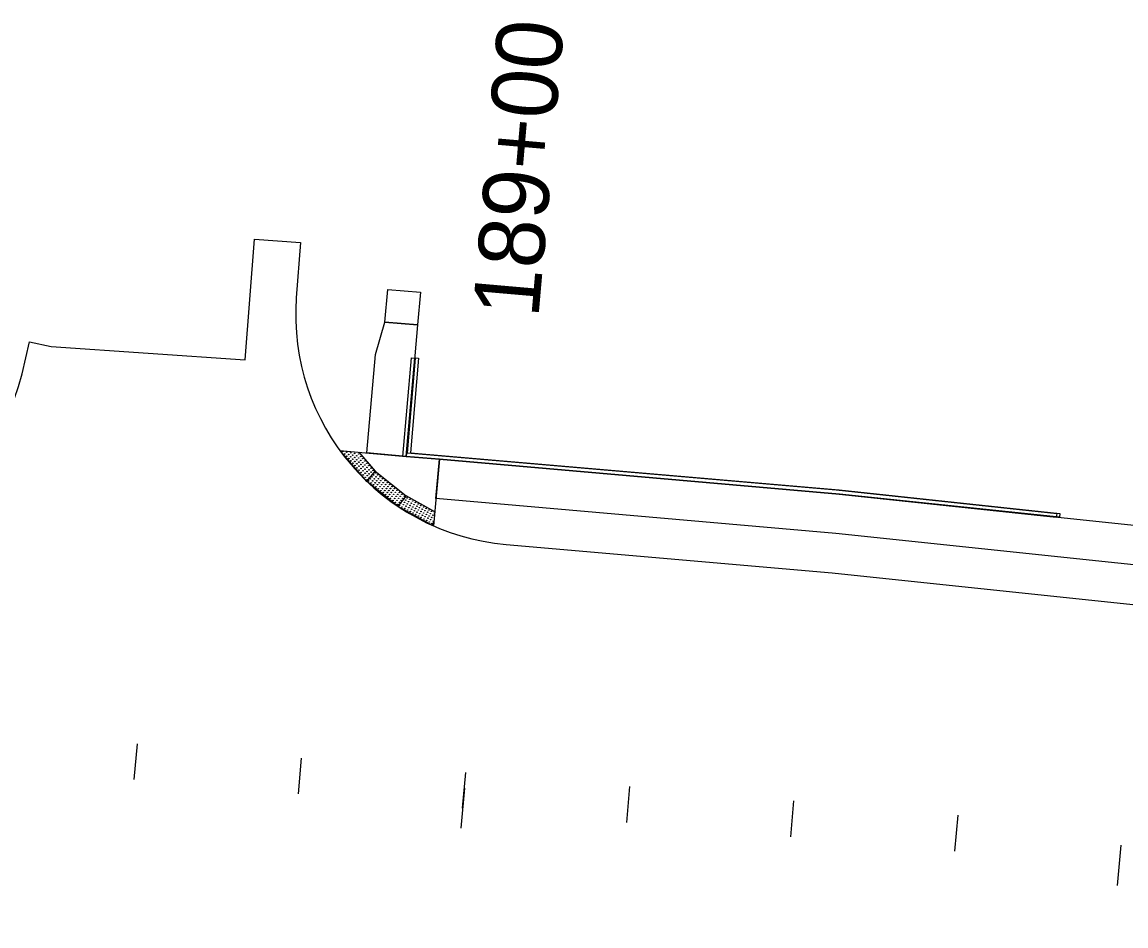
# Model space of a CAD drawing. Extents: x 20499216 to 20505321, y 7953487 to 7960535.
# Drawn here: x 20502538.4 to 20502705.9, y 7953802.5 to 7953939.7 of the extents above; entities that cross this region are included whole.
import ezdxf

# ---------------------------------------------------------------- set-up
doc = ezdxf.new("R2010")
doc.units = 0
for name, color, linetype in [('Drainage', 7, 'Continuous'), ('EXT_CU', 7, 'Continuous'), ('EXT_RR', 7, 'Continuous'), ('EXT_SNP', 7, 'Continuous'), ('NamedBoundary', 7, 'Continuous'), ('Roadways', 7, 'Continuous'), ('Safety', 7, 'Continuous')]:
    doc.layers.add(name, color=color, linetype=linetype)

msp = doc.modelspace()

# ---------------------------------------------------------------- linework, layer by layer
at = {"layer": 'Drainage'}
msp.add_lwpolyline([(20502593.51, 7953894.14), (20502598.46, 7953893.73), (20502596.74, 7953873.78), (20502590.76, 7953874.3), (20502592.07, 7953889.26)], close=True, dxfattribs=at)
at = {"layer": 'EXT_CU'}
for p, q in [((20502586.81, 7953874.5), (20502586.96, 7953874.63)), ((20502590.77, 7953869.99), (20502586.81, 7953874.5)), ((20502589.55, 7953874.41), (20502592.02, 7953871.55)), ((20502590.77, 7953869.99), (20502592.02, 7953871.55)), ((20502592.02, 7953871.55), (20502596.7, 7953867.79)), ((20502595.44, 7953866.23), (20502590.77, 7953869.99)), ((20502596.7, 7953867.79), (20502595.44, 7953866.23)), ((20502601.06, 7953865.39), (20502596.7, 7953867.79)), ((20502595.44, 7953866.23), (20502600.69, 7953863.32)), ((20502600.69, 7953863.32), (20502600.92, 7953863.74))]:
    msp.add_line(p, q, dxfattribs=at)
for points in [[(20502598.61, 7953888.68), (20502597.37, 7953874.31), (20502662.45, 7953868.69), (20502695.94, 7953865.1), (20502695.88, 7953864.54), (20502662.5, 7953868.05), (20502596.74, 7953873.78), (20502598.03, 7953888.73)], [(20502662.5, 7953868.05), (20502961.27, 7953836.6), (20503020.68, 7953827.63), (20503141.39, 7953813.56), (20503176.54, 7953810.63), (20503176.04, 7953804.65), (20503140.79, 7953807.58), (20503019.89, 7953821.68), (20502960.51, 7953830.65), (20502661.92, 7953862.08), (20502601.24, 7953867.37), (20502601.76, 7953873.35)]]:
    msp.add_lwpolyline(points, close=True, dxfattribs=at)
for centre, major_axis in [((20502587.09, 7953874.52), (0.0298, -0.0337)), ((20502587.09, 7953874.52), (0.0149, -0.0169)), ((20502587.4, 7953874.16), (0.0298, -0.0337)), ((20502587.4, 7953874.16), (0.0149, -0.0169)), ((20502587.69, 7953874.42), (0.0298, -0.0337)), ((20502587.71, 7953873.81), (0.0298, -0.0337)), ((20502587.69, 7953874.42), (0.0149, -0.0169)), ((20502587.71, 7953873.81), (0.0149, -0.0169)), ((20502588, 7953874.07), (0.0298, -0.0337)), ((20502588, 7953874.07), (0.0149, -0.0169)), ((20502588.3, 7953874.33), (0.0298, -0.0337)), ((20502588.3, 7953874.33), (0.0149, -0.0169)), ((20502588.31, 7953873.72), (0.0298, -0.0337)), ((20502588.31, 7953873.72), (0.0149, -0.0169)), ((20502588.61, 7953873.97), (0.0298, -0.0337)), ((20502588.61, 7953873.97), (0.0149, -0.0169)), ((20502588.9, 7953874.23), (0.0298, -0.0337)), ((20502588.92, 7953873.62), (0.0298, -0.0337)), ((20502588.9, 7953874.23), (0.0149, -0.0169)), ((20502588.92, 7953873.62), (0.0149, -0.0169)), ((20502589.21, 7953873.88), (0.0298, -0.0337)), ((20502589.21, 7953873.88), (0.0149, -0.0169)), ((20502589.51, 7953874.14), (0.0298, -0.0337)), ((20502589.51, 7953874.14), (0.0149, -0.0169)), ((20502589.82, 7953873.78), (0.0298, -0.0337)), ((20502589.82, 7953873.78), (0.0149, -0.0169)), ((20502588.02, 7953873.46), (0.0298, -0.0337)), ((20502588.02, 7953873.46), (0.0149, -0.0169)), ((20502588.33, 7953873.1), (0.0298, -0.0337)), ((20502588.33, 7953873.1), (0.0149, -0.0169)), ((20502588.62, 7953873.36), (0.0298, -0.0337)), ((20502588.64, 7953872.75), (0.0298, -0.0337)), ((20502588.62, 7953873.36), (0.0149, -0.0169)), ((20502588.64, 7953872.75), (0.0149, -0.0169)), ((20502588.93, 7953873.01), (0.0298, -0.0337)), ((20502588.95, 7953872.4), (0.0298, -0.0337)), ((20502588.93, 7953873.01), (0.0149, -0.0169)), ((20502588.95, 7953872.4), (0.0149, -0.0169)), ((20502589.23, 7953873.27), (0.0298, -0.0337)), ((20502589.23, 7953873.27), (0.0149, -0.0169)), ((20502589.24, 7953872.66), (0.0298, -0.0337)), ((20502589.26, 7953872.04), (0.0298, -0.0337)), ((20502589.24, 7953872.66), (0.0149, -0.0169)), ((20502589.26, 7953872.04), (0.0149, -0.0169)), ((20502589.52, 7953873.53), (0.0298, -0.0337)), ((20502589.54, 7953872.91), (0.0298, -0.0337)), ((20502589.52, 7953873.53), (0.0149, -0.0169)), ((20502589.54, 7953872.91), (0.0149, -0.0169)), ((20502589.55, 7953872.3), (0.0298, -0.0337)), ((20502589.55, 7953872.3), (0.0149, -0.0169)), ((20502589.83, 7953873.17), (0.0298, -0.0337)), ((20502589.85, 7953872.56), (0.0298, -0.0337)), ((20502589.83, 7953873.17), (0.0149, -0.0169)), ((20502589.85, 7953872.56), (0.0149, -0.0169)), ((20502589.86, 7953871.95), (0.0298, -0.0337)), ((20502589.86, 7953871.95), (0.0149, -0.0169)), ((20502590.13, 7953873.43), (0.0298, -0.0337)), ((20502590.13, 7953873.43), (0.0149, -0.0169)), ((20502590.14, 7953872.82), (0.0298, -0.0337)), ((20502590.16, 7953872.21), (0.0298, -0.0337)), ((20502590.14, 7953872.82), (0.0149, -0.0169)), ((20502590.16, 7953872.21), (0.0149, -0.0169)), ((20502590.44, 7953873.08), (0.0298, -0.0337)), ((20502590.44, 7953873.08), (0.0149, -0.0169)), ((20502590.45, 7953872.47), (0.0298, -0.0337)), ((20502590.47, 7953871.85), (0.0298, -0.0337)), ((20502590.45, 7953872.47), (0.0149, -0.0169)), ((20502590.75, 7953872.72), (0.0298, -0.0337)), ((20502590.75, 7953872.72), (0.0149, -0.0169)), ((20502590.76, 7953872.11), (0.0298, -0.0337)), ((20502590.76, 7953872.11), (0.0149, -0.0169)), ((20502591.06, 7953872.37), (0.0298, -0.0337)), ((20502591.06, 7953872.37), (0.0149, -0.0169)), ((20502591.38, 7953872), (0.0298, -0.0337)), ((20502591.38, 7953872), (0.0149, -0.0169)), ((20502589.57, 7953871.69), (0.0298, -0.0337)), ((20502589.57, 7953871.69), (0.0149, -0.0169)), ((20502589.88, 7953871.34), (0.0298, -0.0337)), ((20502589.88, 7953871.34), (0.0149, -0.0169)), ((20502590.17, 7953871.6), (0.0298, -0.0337)), ((20502590.17, 7953871.6), (0.0149, -0.0169)), ((20502590.2, 7953870.97), (0.0298, -0.0337)), ((20502590.2, 7953870.97), (0.0149, -0.0169)), ((20502590.47, 7953871.85), (0.0149, -0.0169)), ((20502590.5, 7953871.22), (0.0298, -0.0337)), ((20502590.51, 7953870.61), (0.0298, -0.0337)), ((20502590.5, 7953871.22), (0.0149, -0.0169)), ((20502590.51, 7953870.61), (0.0149, -0.0169)), ((20502590.79, 7953871.48), (0.0298, -0.0337)), ((20502590.81, 7953870.87), (0.0298, -0.0337)), ((20502590.79, 7953871.48), (0.0149, -0.0169)), ((20502590.82, 7953870.26), (0.0298, -0.0337)), ((20502590.81, 7953870.87), (0.0149, -0.0169)), ((20502590.82, 7953870.26), (0.0149, -0.0169)), ((20502591.09, 7953871.74), (0.0298, -0.0337)), ((20502591.1, 7953871.13), (0.0298, -0.0337)), ((20502591.09, 7953871.74), (0.0149, -0.0169)), ((20502591.12, 7953870.52), (0.0298, -0.0337)), ((20502591.1, 7953871.13), (0.0149, -0.0169)), ((20502591.12, 7953870.52), (0.0149, -0.0169)), ((20502591.28, 7953870.36), (0.0352, -0.0281)), ((20502591.28, 7953870.36), (0.0176, -0.014)), ((20502591.4, 7953871.39), (0.0298, -0.0337)), ((20502591.4, 7953871.39), (0.0149, -0.0169)), ((20502591.53, 7953870.67), (0.0352, -0.0281)), ((20502591.53, 7953870.67), (0.0176, -0.014)), ((20502591.69, 7953871.65), (0.0298, -0.0337)), ((20502591.69, 7953871.65), (0.0149, -0.0169)), ((20502591.78, 7953870.97), (0.0352, -0.0281)), ((20502591.78, 7953870.97), (0.0176, -0.014)), ((20502591.9, 7953870.37), (0.0352, -0.0281)), ((20502591.9, 7953870.37), (0.0176, -0.014)), ((20502592.02, 7953871.28), (0.0352, -0.0281)), ((20502592.02, 7953871.28), (0.0176, -0.014)), ((20502592.14, 7953870.68), (0.0352, -0.0281)), ((20502592.14, 7953870.68), (0.0176, -0.014)), ((20502592.39, 7953870.98), (0.0352, -0.0281)), ((20502592.39, 7953870.98), (0.0176, -0.014)), ((20502592.51, 7953870.38), (0.0352, -0.0281)), ((20502592.51, 7953870.38), (0.0176, -0.014)), ((20502592.75, 7953870.69), (0.0352, -0.0281)), ((20502592.75, 7953870.69), (0.0176, -0.014)), ((20502593.12, 7953870.39), (0.0352, -0.0281)), ((20502593.12, 7953870.39), (0.0176, -0.014)), ((20502591.04, 7953870.06), (0.0352, -0.0281)), ((20502591.04, 7953870.06), (0.0176, -0.014)), ((20502591.41, 7953869.76), (0.0352, -0.0281)), ((20502591.41, 7953869.76), (0.0176, -0.014)), ((20502591.65, 7953870.07), (0.0352, -0.0281)), ((20502591.65, 7953870.07), (0.0176, -0.014)), ((20502591.77, 7953869.47), (0.0352, -0.0281)), ((20502591.77, 7953869.47), (0.0176, -0.014)), ((20502592.02, 7953869.77), (0.0352, -0.0281)), ((20502592.02, 7953869.77), (0.0176, -0.014)), ((20502592.14, 7953869.17), (0.0352, -0.0281)), ((20502592.14, 7953869.17), (0.0176, -0.014)), ((20502592.26, 7953870.08), (0.0352, -0.0281)), ((20502592.26, 7953870.08), (0.0176, -0.014)), ((20502592.38, 7953869.48), (0.0352, -0.0281)), ((20502592.38, 7953869.48), (0.0176, -0.014)), ((20502592.5, 7953868.88), (0.0352, -0.0281)), ((20502592.5, 7953868.88), (0.0176, -0.014)), ((20502592.63, 7953869.78), (0.0352, -0.0281)), ((20502592.63, 7953869.78), (0.0176, -0.014)), ((20502592.75, 7953869.18), (0.0352, -0.0281)), ((20502592.75, 7953869.18), (0.0176, -0.014)), ((20502592.87, 7953868.58), (0.0352, -0.0281)), ((20502592.88, 7953870.09), (0.0352, -0.0281)), ((20502592.88, 7953870.09), (0.0176, -0.014)), ((20502592.87, 7953868.58), (0.0176, -0.014)), ((20502593, 7953869.49), (0.0352, -0.0281)), ((20502593, 7953869.49), (0.0176, -0.014)), ((20502593.12, 7953868.89), (0.0352, -0.0281)), ((20502593.12, 7953868.89), (0.0176, -0.014)), ((20502593.24, 7953869.79), (0.0352, -0.0281)), ((20502593.24, 7953869.79), (0.0176, -0.014)), ((20502593.36, 7953869.19), (0.0352, -0.0281)), ((20502593.36, 7953869.19), (0.0176, -0.014)), ((20502593.48, 7953868.59), (0.0352, -0.0281)), ((20502593.49, 7953870.1), (0.0352, -0.0281)), ((20502593.49, 7953870.1), (0.0176, -0.014)), ((20502593.48, 7953868.59), (0.0176, -0.014)), ((20502593.61, 7953869.5), (0.0352, -0.0281)), ((20502593.61, 7953869.5), (0.0176, -0.014)), ((20502593.73, 7953868.9), (0.0352, -0.0281)), ((20502593.73, 7953868.9), (0.0176, -0.014)), ((20502593.85, 7953869.8), (0.0352, -0.0281)), ((20502593.85, 7953869.8), (0.0176, -0.014)), ((20502593.97, 7953869.2), (0.0352, -0.0281)), ((20502593.97, 7953869.2), (0.0176, -0.014)), ((20502594.09, 7953868.6), (0.0352, -0.0281)), ((20502594.09, 7953868.6), (0.0176, -0.014)), ((20502594.22, 7953869.51), (0.0352, -0.0281)), ((20502594.22, 7953869.51), (0.0176, -0.014)), ((20502594.34, 7953868.91), (0.0352, -0.0281)), ((20502594.34, 7953868.91), (0.0176, -0.014)), ((20502594.59, 7953869.21), (0.0352, -0.0281)), ((20502594.59, 7953869.21), (0.0176, -0.014)), ((20502594.71, 7953868.61), (0.0352, -0.0281)), ((20502594.71, 7953868.61), (0.0176, -0.014)), ((20502594.95, 7953868.92), (0.0352, -0.0281)), ((20502594.95, 7953868.92), (0.0176, -0.014)), ((20502595.32, 7953868.63), (0.0352, -0.0281)), ((20502595.32, 7953868.63), (0.0176, -0.014)), ((20502593.24, 7953868.29), (0.0352, -0.0281)), ((20502593.24, 7953868.29), (0.0176, -0.014)), ((20502593.6, 7953867.99), (0.0352, -0.0281)), ((20502593.6, 7953867.99), (0.0176, -0.014)), ((20502593.85, 7953868.3), (0.0352, -0.0281)), ((20502593.85, 7953868.3), (0.0176, -0.014)), ((20502593.97, 7953867.7), (0.0352, -0.0281)), ((20502593.97, 7953867.7), (0.0176, -0.014)), ((20502594.21, 7953868), (0.0352, -0.0281)), ((20502594.21, 7953868), (0.0176, -0.014)), ((20502594.33, 7953867.41), (0.0352, -0.0281)), ((20502594.33, 7953867.41), (0.0176, -0.014)), ((20502594.46, 7953868.31), (0.0352, -0.0281)), ((20502594.46, 7953868.31), (0.0176, -0.014)), ((20502594.58, 7953867.71), (0.0352, -0.0281)), ((20502594.58, 7953867.71), (0.0176, -0.014)), ((20502594.72, 7953867.1), (0.0352, -0.0281)), ((20502594.72, 7953867.1), (0.0176, -0.014)), ((20502594.83, 7953868.02), (0.0352, -0.0281)), ((20502594.83, 7953868.02), (0.0176, -0.014)), ((20502594.97, 7953867.4), (0.0352, -0.0281)), ((20502594.97, 7953867.4), (0.0176, -0.014)), ((20502595.07, 7953868.32), (0.0352, -0.0281)), ((20502595.07, 7953868.32), (0.0176, -0.014)), ((20502595.21, 7953867.71), (0.0352, -0.0281)), ((20502595.21, 7953867.71), (0.0176, -0.014)), ((20502595.33, 7953867.11), (0.0352, -0.0281)), ((20502595.33, 7953867.11), (0.0176, -0.014)), ((20502595.46, 7953868.01), (0.0352, -0.0281)), ((20502595.46, 7953868.01), (0.0176, -0.014)), ((20502595.58, 7953867.41), (0.0352, -0.0281)), ((20502595.58, 7953867.41), (0.0176, -0.014)), ((20502595.7, 7953868.31), (0.0352, -0.0281)), ((20502595.7, 7953868.31), (0.0176, -0.014)), ((20502595.82, 7953867.72), (0.0352, -0.0281)), ((20502595.82, 7953867.72), (0.0176, -0.014)), ((20502595.94, 7953867.12), (0.0352, -0.0281)), ((20502595.94, 7953867.12), (0.0176, -0.014)), ((20502596.07, 7953868.02), (0.0352, -0.0281)), ((20502596.07, 7953868.02), (0.0176, -0.014)), ((20502596.19, 7953867.42), (0.0352, -0.0281)), ((20502596.19, 7953867.42), (0.0176, -0.014)), ((20502596.44, 7953867.73), (0.0352, -0.0281)), ((20502596.44, 7953867.73), (0.0176, -0.014)), ((20502596.67, 7953867.14), (-0.0393, 0.0219)), ((20502596.67, 7953867.14), (-0.0197, 0.0109)), ((20502596.86, 7953867.48), (-0.0393, 0.0219)), ((20502596.86, 7953867.48), (-0.0197, 0.0109)), ((20502597.08, 7953866.91), (-0.0393, 0.0219)), ((20502597.08, 7953866.91), (-0.0197, 0.0109)), ((20502597.27, 7953867.26), (-0.0393, 0.0219)), ((20502597.27, 7953867.26), (-0.0197, 0.0109)), ((20502597.7, 7953867.02), (-0.0393, 0.0219)), ((20502597.7, 7953867.02), (-0.0197, 0.0109)), ((20502595.09, 7953866.8), (0.0352, -0.0281)), ((20502595.09, 7953866.8), (0.0176, -0.014)), ((20502595.45, 7953866.51), (0.0352, -0.0281)), ((20502595.45, 7953866.51), (0.0176, -0.014)), ((20502595.69, 7953866.34), (-0.0393, 0.0219)), ((20502595.7, 7953866.81), (0.0352, -0.0281)), ((20502595.7, 7953866.81), (0.0176, -0.014)), ((20502595.69, 7953866.34), (-0.0197, 0.0109)), ((20502595.88, 7953866.68), (-0.0393, 0.0219)), ((20502595.88, 7953866.68), (-0.0197, 0.0109)), ((20502596.1, 7953866.11), (-0.0393, 0.0219)), ((20502596.1, 7953866.11), (-0.0197, 0.0109)), ((20502596.29, 7953866.45), (-0.0393, 0.0219)), ((20502596.29, 7953866.45), (-0.0197, 0.0109)), ((20502596.48, 7953866.8), (-0.0393, 0.0219)), ((20502596.48, 7953866.8), (-0.0197, 0.0109)), ((20502596.51, 7953865.88), (-0.0393, 0.0219)), ((20502596.51, 7953865.88), (-0.0197, 0.0109)), ((20502596.7, 7953866.23), (-0.0393, 0.0219)), ((20502596.7, 7953866.23), (-0.0197, 0.0109)), ((20502596.89, 7953866.57), (-0.0393, 0.0219)), ((20502596.89, 7953866.57), (-0.0197, 0.0109)), ((20502596.95, 7953865.64), (-0.0393, 0.0219)), ((20502596.95, 7953865.64), (-0.0197, 0.0109)), ((20502597.14, 7953865.99), (-0.0393, 0.0219)), ((20502597.14, 7953865.99), (-0.0197, 0.0109)), ((20502597.32, 7953866.33), (-0.0393, 0.0219)), ((20502597.32, 7953866.33), (-0.0197, 0.0109)), ((20502597.36, 7953865.42), (-0.0393, 0.0219)), ((20502597.36, 7953865.42), (-0.0197, 0.0109)), ((20502597.51, 7953866.67), (-0.0393, 0.0219)), ((20502597.51, 7953866.67), (-0.0197, 0.0109)), ((20502597.55, 7953865.76), (-0.0393, 0.0219)), ((20502597.55, 7953865.76), (-0.0197, 0.0109)), ((20502597.74, 7953866.1), (-0.0393, 0.0219)), ((20502597.74, 7953866.1), (-0.0197, 0.0109)), ((20502597.77, 7953865.19), (-0.0393, 0.0219)), ((20502597.77, 7953865.19), (-0.0197, 0.0109)), ((20502597.92, 7953866.45), (-0.0393, 0.0219)), ((20502597.92, 7953866.45), (-0.0197, 0.0109)), ((20502597.96, 7953865.53), (-0.0393, 0.0219)), ((20502597.96, 7953865.53), (-0.0197, 0.0109)), ((20502598.11, 7953866.79), (-0.0393, 0.0219)), ((20502598.11, 7953866.79), (-0.0197, 0.0109)), ((20502598.15, 7953865.88), (-0.0393, 0.0219)), ((20502598.15, 7953865.88), (-0.0197, 0.0109)), ((20502598.34, 7953866.22), (-0.0393, 0.0219)), ((20502598.34, 7953866.22), (-0.0197, 0.0109)), ((20502598.37, 7953865.31), (-0.0393, 0.0219)), ((20502598.37, 7953865.31), (-0.0197, 0.0109)), ((20502598.53, 7953866.56), (-0.0393, 0.0219)), ((20502598.53, 7953866.56), (-0.0197, 0.0109)), ((20502598.56, 7953865.65), (-0.0393, 0.0219)), ((20502598.56, 7953865.65), (-0.0197, 0.0109)), ((20502598.75, 7953865.99), (-0.0393, 0.0219)), ((20502598.75, 7953865.99), (-0.0197, 0.0109)), ((20502598.94, 7953866.33), (-0.0393, 0.0219)), ((20502598.94, 7953866.33), (-0.0197, 0.0109)), ((20502598.97, 7953865.42), (-0.0393, 0.0219)), ((20502598.97, 7953865.42), (-0.0197, 0.0109)), ((20502599.16, 7953865.76), (-0.0393, 0.0219)), ((20502599.16, 7953865.76), (-0.0197, 0.0109)), ((20502599.35, 7953866.11), (-0.0393, 0.0219)), ((20502599.35, 7953866.11), (-0.0197, 0.0109)), ((20502599.38, 7953865.19), (-0.0393, 0.0219)), ((20502599.38, 7953865.19), (-0.0197, 0.0109)), ((20502599.57, 7953865.54), (-0.0393, 0.0219)), ((20502599.57, 7953865.54), (-0.0197, 0.0109)), ((20502599.76, 7953865.88), (-0.0393, 0.0219)), ((20502599.76, 7953865.88), (-0.0197, 0.0109)), ((20502599.98, 7953865.31), (-0.0393, 0.0219)), ((20502599.98, 7953865.31), (-0.0197, 0.0109)), ((20502600.17, 7953865.65), (-0.0393, 0.0219)), ((20502600.17, 7953865.65), (-0.0197, 0.0109)), ((20502600.58, 7953865.43), (-0.0393, 0.0219)), ((20502600.58, 7953865.43), (-0.0197, 0.0109)), ((20502600.99, 7953865.2), (-0.0393, 0.0219)), ((20502600.99, 7953865.2), (-0.0197, 0.0109)), ((20502598.18, 7953864.96), (-0.0393, 0.0219)), ((20502598.18, 7953864.96), (-0.0197, 0.0109)), ((20502598.59, 7953864.74), (-0.0393, 0.0219)), ((20502598.59, 7953864.74), (-0.0197, 0.0109)), ((20502598.78, 7953865.08), (-0.0393, 0.0219)), ((20502598.78, 7953865.08), (-0.0197, 0.0109)), ((20502599, 7953864.51), (-0.0393, 0.0219)), ((20502599, 7953864.51), (-0.0197, 0.0109)), ((20502599.19, 7953864.85), (-0.0393, 0.0219)), ((20502599.19, 7953864.85), (-0.0197, 0.0109)), ((20502599.42, 7953864.28), (-0.0393, 0.0219)), ((20502599.42, 7953864.28), (-0.0197, 0.0109)), ((20502599.6, 7953864.62), (-0.0393, 0.0219)), ((20502599.6, 7953864.62), (-0.0197, 0.0109)), ((20502599.79, 7953864.97), (-0.0393, 0.0219)), ((20502599.79, 7953864.97), (-0.0197, 0.0109)), ((20502599.83, 7953864.05), (-0.0393, 0.0219)), ((20502599.83, 7953864.05), (-0.0197, 0.0109)), ((20502600.02, 7953864.4), (-0.0393, 0.0219)), ((20502600.02, 7953864.4), (-0.0197, 0.0109)), ((20502600.2, 7953864.74), (-0.0393, 0.0219)), ((20502600.2, 7953864.74), (-0.0197, 0.0109)), ((20502600.24, 7953863.83), (-0.0393, 0.0219)), ((20502600.24, 7953863.83), (-0.0197, 0.0109)), ((20502600.39, 7953865.08), (-0.0393, 0.0219)), ((20502600.39, 7953865.08), (-0.0197, 0.0109)), ((20502600.43, 7953864.17), (-0.0393, 0.0219)), ((20502600.43, 7953864.17), (-0.0197, 0.0109)), ((20502600.62, 7953864.51), (-0.0393, 0.0219)), ((20502600.62, 7953864.51), (-0.0197, 0.0109)), ((20502600.65, 7953863.6), (-0.0393, 0.0219)), ((20502600.65, 7953863.6), (-0.0197, 0.0109)), ((20502600.8, 7953864.86), (-0.0393, 0.0219)), ((20502600.8, 7953864.86), (-0.0197, 0.0109)), ((20502600.84, 7953863.94), (-0.0393, 0.0219)), ((20502600.84, 7953863.94), (-0.0197, 0.0109))]:
    msp.add_ellipse(centre, major_axis=major_axis, ratio=0.833333, dxfattribs=at)
at = {"layer": 'EXT_RR'}
for p, q in [((20502555.47, 7953824.71), (20502555.95, 7953830.15)), ((20502580.38, 7953822.54), (20502580.85, 7953827.98)), ((20502605.55, 7953823.43), (20502605.02, 7953817.33)), ((20502630.19, 7953818.21), (20502630.66, 7953823.65)), ((20502655.1, 7953816.04), (20502655.57, 7953821.48)), ((20502680, 7953813.87), (20502680.47, 7953819.31)), ((20502705.17, 7953814.76), (20502704.64, 7953808.66))]:
    msp.add_line(p, q, dxfattribs=at)
at = {"layer": 'EXT_SNP'}
for points in [[(20502598.11, 7953888.67), (20502596.87, 7953874.3), (20502661.95, 7953868.68), (20502695.44, 7953865.09), (20502695.38, 7953864.53), (20502662, 7953868.04), (20502601.26, 7953873.34), (20502601.26, 7953873.34), (20502596.24, 7953873.77), (20502597.53, 7953888.72)], [(20502598.61, 7953888.68), (20502597.37, 7953874.31), (20502662.45, 7953868.69), (20502695.94, 7953865.1), (20502695.88, 7953864.54), (20502662.5, 7953868.05), (20502601.76, 7953873.35), (20502601.76, 7953873.35), (20502596.74, 7953873.78), (20502598.03, 7953888.73)]]:
    msp.add_lwpolyline(points, close=True, dxfattribs=at)
at = {"layer": 'NamedBoundary'}
for points in [[(20502538.44, 7953886.33), (20502539.55, 7953891.17), (20502542.86, 7953890.48), (20502572.28, 7953888.46), (20502573.71, 7953906.78), (20502580.67, 7953906.24), (20502580.05, 7953897.86)], [(20502611.92, 7953860.41), (20502661.35, 7953856.11), (20502959.75, 7953824.69), (20503138.13, 7953797.77), (20503167.85, 7953795.29), (20503167.85, 7953795.29)]]:
    msp.add_lwpolyline(points, dxfattribs=at)
for centre, radius, start, end in [((20502614.96, 7953895.28), 35, 175.7813, 265.0212), ((20502494.97, 7953897.61), 44.91, 265.731, 345.4565)]:
    msp.add_arc(centre, radius, start, end, dxfattribs=at)
at = {"layer": 'Roadways'}
msp.add_lwpolyline([(20502598.88, 7953898.71), (20502598.46, 7953893.73), (20502593.51, 7953894.14), (20502593.94, 7953899.12)], close=True, dxfattribs=at)
msp.add_lwpolyline([(20502586.68, 7953874.66), (20502596.74, 7953873.78), (20502601.76, 7953873.35), (20502600.88, 7953863.24)], dxfattribs=at)
msp.add_arc((20502614.96, 7953895.28), 35, 216.1035, 246.2755, dxfattribs=at)
at = {"layer": 'Safety'}
for p, q in [((20502605.28, 7953820.38), (20502605.76, 7953825.82)), ((20502705.17, 7953814.76), (20502704.64, 7953808.66))]:
    msp.add_line(p, q, dxfattribs=at)

# ---------------------------------------------------------------- texts
at = {"layer": 'EXT_RR'}
msp.add_text('189+00', height=10.02, rotation=85.0264, dxfattribs=at).set_placement((20502616.78, 7953894.66))

doc.saveas('drawing.dxf')
